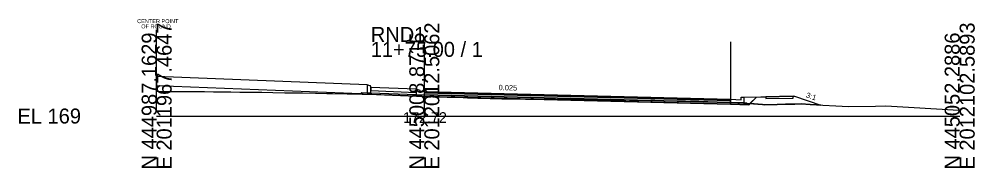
# Model space of a CAD drawing. Extents: x -26 to 153, y -10 to 6017.
# Drawn here: x -25.7 to 152.8, y 3490.3 to 3518.1 of the extents above; entities that cross this region are included whole.
import ezdxf

# ---------------------------------------------------------------- set-up
doc = ezdxf.new("R2010")
doc.units = 0
for name, color, linetype in [('Exist Cross Section Cell', 7, 'Continuous'), ('Exist XS Ground Line', 7, 'Continuous'), ('Prop CMT Conc Surface', 7, 'Continuous'), ('Prop CMT Concrete Structures', 7, 'Continuous'), ('Prop CMT Pvmt Course 1', 7, 'Continuous'), ('Prop CMT Pvmt Course 1 CG', 7, 'Continuous'), ('Prop CMT Pvmt Course 2', 7, 'Continuous'), ('Prop CMT Pvmt Course 3', 7, 'Continuous'), ('Prop CMT Pvmt Surface', 7, 'Continuous'), ('Prop CMT Shear Line', 7, 'Continuous'), ('Prop CMT Shear Line Text', 7, 'Continuous'), ('Prop CMT Slope Grass', 7, 'Continuous'), ('Prop CMT Subgrade Earthwork', 7, 'Continuous'), ('Prop XS Earthwork Shape', 7, 'Continuous'), ('Prop XS SE Text', 7, 'Continuous'), ('Prop XS Side Slope Text', 7, 'Continuous'), ('Scratch_Level_1', 7, 'Continuous')]:
    doc.layers.add(name, color=color, linetype=linetype)

msp = doc.modelspace()

# ---------------------------------------------------------------- linework, layer by layer
at = {"layer": 'Exist Cross Section Cell'}
for p, q in [((50, 3500), (50, 3513.86)), ((0, 3500), (50, 3500)), ((50, 3500), (150, 3500))]:
    msp.add_line(p, q, dxfattribs=at)
at = {"layer": 'Exist XS Ground Line'}
msp.add_lwpolyline([(0, 3504.62), (0.96, 3504.61), (1.85, 3504.61), (2.28, 3504.61), (3.53, 3504.61), (5.06, 3504.6), (6.67, 3504.6), (7.83, 3504.58), (8.94, 3504.56), (10.6, 3504.53), (11.18, 3504.52), (12.37, 3504.51), (13.22, 3504.5), (13.86, 3504.5), (15.53, 3504.49), (17.42, 3504.49), (17.97, 3504.48), (18.93, 3504.45), (19.63, 3504.44), (21.7, 3504.4), (23.93, 3504.36), (24.49, 3504.36), (25.01, 3504.35), (27.26, 3504.31), (29.66, 3504.27), (30.03, 3504.27), (31.79, 3504.23), (32.82, 3504.21), (35.58, 3504.16), (37.4, 3504.13), (38.37, 3504.11), (39.3, 3504.09), (41.27, 3504.05), (43.94, 3503.97), (46.95, 3503.86), (48.61, 3503.79), (49.43, 3503.74), (50, 3503.72), (51.86, 3503.64), (52.68, 3503.6), (54.27, 3503.55), (55.03, 3503.52), (57.23, 3503.45), (58.04, 3503.43), (58.52, 3503.41), (59.97, 3503.36), (60.56, 3503.34), (62.32, 3503.29), (63.36, 3503.26), (64.5, 3503.24), (66.2, 3503.21), (67.67, 3503.2), (68.87, 3503.18), (70.13, 3503.17), (71.63, 3503.16), (73.16, 3503.15), (74.49, 3503.13), (75.92, 3503.12), (76.73, 3503.12), (77.11, 3503.12), (78.8, 3503.09), (80.04, 3503.08), (81.69, 3503.06), (82.77, 3503.04), (83.86, 3503.03), (85.55, 3503.02), (86.12, 3503.02), (87.27, 3503), (88.33, 3502.99), (89.86, 3502.97), (91.11, 3502.97), (93.04, 3502.94), (93.88, 3502.92), (94.66, 3502.91), (96.65, 3502.87), (97.35, 3502.86), (98.81, 3502.83), (99.41, 3502.81), (99.97, 3502.79), (102.17, 3502.72), (102.95, 3502.7), (104.94, 3502.62), (105.3, 3502.61), (107.72, 3502.53), (108.57, 3502.48), (110.61, 3502.34), (113.16, 3502.15), (113.5, 3502.11), (115.89, 3502.17), (119.2, 3502.24), (120.36, 3502.27), (122.07, 3502.15), (129.22, 3501.77), (134.28, 3501.84), (136.22, 3501.88), (141.48, 3501.58), (148.8, 3501.16), (150, 3501.12)], dxfattribs=at)
at = {"layer": 'Prop CMT Conc Surface'}
for points in [[(40, 3505.52), (39.96, 3505.63), (39.85, 3505.67), (39.34, 3505.86)], [(40, 3505.36), (40, 3505.52)], [(50, 3504.56), (49.25, 3504.58), (49.25, 3504.75), (48.5, 3505)], [(107.19, 3503.13), (109.18, 3503)], [(109.18, 3503), (109.18, 3503.5), (109.68, 3503.5)], [(113.79, 3503.59), (118.79, 3503.69)]]:
    msp.add_lwpolyline(points, dxfattribs=at)
at = {"layer": 'Prop CMT Concrete Structures'}
for points in [[(40, 3505.52), (39.96, 3505.63), (39.85, 3505.67), (39.34, 3505.86)], [(39.34, 3505.86), (39.34, 3504.36)], [(40, 3505.36), (40, 3505.52)], [(40, 3504.36), (40, 3505.36)], [(40, 3505.36), (40, 3504.77)], [(48.5, 3505), (40, 3505.34)], [(40, 3504.75), (48.5, 3504.41)], [(50, 3504.56), (49.25, 3504.58), (49.25, 3504.75), (48.5, 3505)], [(48.5, 3505), (48.5, 3504.02)], [(48.5, 3504.41), (48.5, 3505)], [(39.34, 3504.36), (40, 3504.36)], [(48.5, 3504.02), (50, 3503.98)], [(50, 3503.98), (50, 3504.56)], [(107.19, 3503.13), (109.18, 3503), (109.18, 3503.5), (109.68, 3503.5)], [(109.68, 3503.5), (109.68, 3502.48), (107.19, 3502.54)], [(107.19, 3502.54), (107.19, 3503.13)], [(118.88, 3503.69), (113.79, 3503.59)], [(113.79, 3503.59), (113.79, 3503.26)], [(113.79, 3503.26), (118.88, 3503.36)], [(118.88, 3503.36), (118.88, 3503.69)]]:
    msp.add_lwpolyline(points, dxfattribs=at)
at = {"layer": 'Prop CMT Pvmt Course 1'}
for points in [[(50, 3504.56), (107.19, 3503.13)], [(50, 3504.31), (50, 3504.56)], [(107.19, 3502.88), (50, 3504.31)], [(107.19, 3503.13), (107.19, 3502.88)]]:
    msp.add_lwpolyline(points, dxfattribs=at)
msp.add_lwpolyline([(50, 3504.31), (50, 3504.44), (50, 3504.44), (50, 3504.31)], close=True, dxfattribs=at)
at = {"layer": 'Prop CMT Pvmt Course 1 CG'}
for points in [[(50, 3503.64), (50, 3503.98)], [(107.19, 3502.54), (110.18, 3502.47), (110.52, 3502.13)], [(107.19, 3502.21), (107.19, 3502.54)], [(110.6, 3502.12), (107.19, 3502.21)]]:
    msp.add_lwpolyline(points, dxfattribs=at)
at = {"layer": 'Prop CMT Pvmt Course 2'}
for points in [[(50, 3503.98), (50, 3504.31)], [(50, 3504.31), (107.19, 3502.88)], [(107.19, 3502.54), (50, 3503.98)], [(107.19, 3502.88), (107.19, 3502.54)]]:
    msp.add_lwpolyline(points, dxfattribs=at)
at = {"layer": 'Prop CMT Pvmt Course 3'}
for points in [[(40, 3504.36), (48.5, 3504.02)], [(50, 3503.98), (107.19, 3502.54)], [(50, 3503.64), (50, 3503.98)], [(107.19, 3502.21), (50, 3503.64)], [(107.19, 3502.54), (107.19, 3502.21)]]:
    msp.add_lwpolyline(points, dxfattribs=at)
at = {"layer": 'Prop CMT Pvmt Surface'}
msp.add_lwpolyline([(50, 3504.56), (107.19, 3503.13)], dxfattribs=at)
at = {"layer": 'Prop CMT Shear Line'}
msp.add_line((0, 3501.1), (0, 3516.1), dxfattribs=at)
at = {"layer": 'Prop CMT Slope Grass'}
for p, q in [((39.34, 3505.84), (0, 3507.41)), ((38.06, 3504.12), (0, 3505.65))]:
    msp.add_line(p, q, dxfattribs=at)
msp.add_lwpolyline([(109.68, 3503.5), (119.15, 3503.69), (124.06, 3502.05)], dxfattribs=at)
at = {"layer": 'Prop CMT Subgrade Earthwork'}
for p, q in [((0, 3507.41), (0, 3504.62)), ((38.34, 3504.4), (38.06, 3504.12))]:
    msp.add_line(p, q, dxfattribs=at)
for points in [[(38.06, 3504.12), (50, 3503.64)], [(38.34, 3504.4), (39.34, 3504.36)], [(50, 3503.64), (107.19, 3502.21)], [(107.19, 3502.21), (110.6, 3502.12), (112.02, 3503.54)]]:
    msp.add_lwpolyline(points, dxfattribs=at)
at = {"layer": 'Prop XS Earthwork Shape'}
for points in [[(0.96, 3504.61), (1.85, 3504.61), (2.28, 3504.61), (3.53, 3504.61), (5.06, 3504.6), (6.67, 3504.6), (7.83, 3504.58), (8.94, 3504.56), (10.6, 3504.53), (11.18, 3504.52), (12.37, 3504.51), (13.22, 3504.5), (13.86, 3504.5), (15.53, 3504.49), (17.42, 3504.49), (17.97, 3504.48), (18.93, 3504.45), (19.63, 3504.44), (21.7, 3504.4), (23.93, 3504.36), (24.49, 3504.36), (25.01, 3504.35), (27.26, 3504.31), (29.66, 3504.27), (30.03, 3504.27), (31.79, 3504.23), (32.82, 3504.21), (35.58, 3504.16), (37.4, 3504.13), (38.37, 3504.11), (38.58, 3504.1), (38.06, 3504.12), (0, 3505.65), (0, 3504.62)], [(38.58, 3504.1), (39.3, 3504.09), (41.27, 3504.05), (43.94, 3503.97), (46.95, 3503.86), (48.61, 3503.79), (49.43, 3503.74), (50, 3503.72), (51.86, 3503.64), (52.68, 3503.6), (54.27, 3503.55), (55.03, 3503.52), (55.72, 3503.5), (50, 3503.64)], [(55.72, 3503.5), (57.23, 3503.45), (58.04, 3503.43), (58.52, 3503.41), (59.97, 3503.36), (60.56, 3503.34), (62.32, 3503.29), (63.36, 3503.26), (64.5, 3503.24), (66.2, 3503.21), (67.67, 3503.2), (67.88, 3503.2)], [(67.88, 3503.2), (68.87, 3503.18), (70.13, 3503.17), (71.63, 3503.16), (73.16, 3503.15), (74.49, 3503.13), (75.92, 3503.12), (76.73, 3503.12), (77.11, 3503.12), (78.8, 3503.09), (80.04, 3503.08), (81.69, 3503.06), (82.77, 3503.04), (83.86, 3503.03), (85.55, 3503.02), (86.12, 3503.02), (87.27, 3503), (88.33, 3502.99), (89.86, 3502.97), (91.11, 3502.97), (93.04, 3502.94), (93.88, 3502.92), (94.66, 3502.91), (96.65, 3502.87), (97.35, 3502.86), (97.5, 3502.85), (97.5, 3502.79), (99.99, 3502.72), (99.99, 3502.79), (101.3, 3502.75), (104.94, 3502.62), (107.72, 3502.53), (110.61, 3502.34), (110.81, 3502.33), (110.6, 3502.12), (97.5, 3502.45)], [(97.5, 3502.85), (98.81, 3502.83), (99.41, 3502.81), (99.97, 3502.79), (99.99, 3502.79), (99.99, 3502.72), (97.5, 3502.79)], [(118.88, 3503.69), (119.15, 3503.69), (124.06, 3502.05), (122.07, 3502.15), (120.36, 3502.27), (119.2, 3502.24), (117.45, 3502.2), (115.89, 3502.17), (113.5, 3502.11), (113.16, 3502.15), (110.81, 3502.33), (112.02, 3503.54), (113.79, 3503.59), (113.79, 3503.26), (118.88, 3503.36)]]:
    msp.add_lwpolyline(points, close=True, dxfattribs=at)
at = {"layer": 'Scratch_Level_1'}
msp.add_line((107.19, 3513.86), (107.19, 3503.13), dxfattribs=at)

# ---------------------------------------------------------------- texts
at = {"layer": 'Exist Cross Section Cell'}
for s, p in [('E 2011967.4647', (2.8, 3490)), ('E 2012012.5062', (52.8, 3490)), ('E 2012102.5893', (152.8, 3490)), ('N 444987.1629', (0, 3490)), ('N 445008.8715', (50, 3490)), ('N 445052.2886', (150, 3490))]:
    msp.add_text(s, height=2.8, rotation=90, dxfattribs=at).set_placement(p)
for s, p in [('RND1', (40, 3513.86)), ('11+75.00 / 1', (40, 3511.06)), ('EL 169', (-26, 3498.6))]:
    msp.add_text(s, height=2.8, dxfattribs=at).set_placement(p)
at = {"layer": 'Exist XS Ground Line'}
msp.add_text('172.72', height=2, dxfattribs=at).set_placement((46.03, 3498.72))
at = {"layer": 'Prop CMT Shear Line Text'}
for s, p in [('CENTER POINT', (-3.64, 3517.36)), ('OF ROUND', (-2.88, 3516.38))]:
    msp.add_text(s, height=0.75, dxfattribs=at).set_placement(p)
at = {"layer": 'Prop XS SE Text'}
msp.add_text('0.025', height=1, rotation=358.5613, dxfattribs=at).set_placement((63.87, 3504.84))
at = {"layer": 'Prop XS Side Slope Text'}
msp.add_text('3:1', height=1, rotation=341.5651, dxfattribs=at).set_placement((121.22, 3503.51))

doc.saveas('drawing.dxf')
